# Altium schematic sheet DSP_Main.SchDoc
size A4
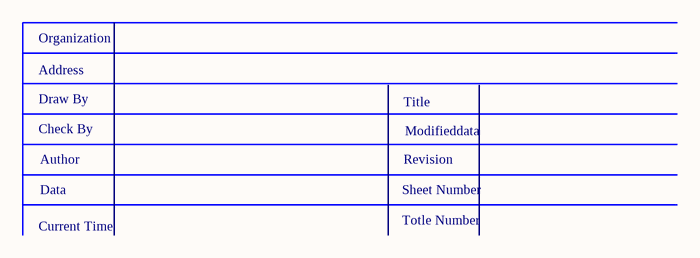
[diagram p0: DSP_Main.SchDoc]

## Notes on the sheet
- Organization
- Draw By
- Check By
- Address
- Title
- Modifieddata
- Data
- Author
- Sheet Number
- Revision
- Current Time
- Totle Number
